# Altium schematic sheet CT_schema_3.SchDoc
size 461 x 327 mm
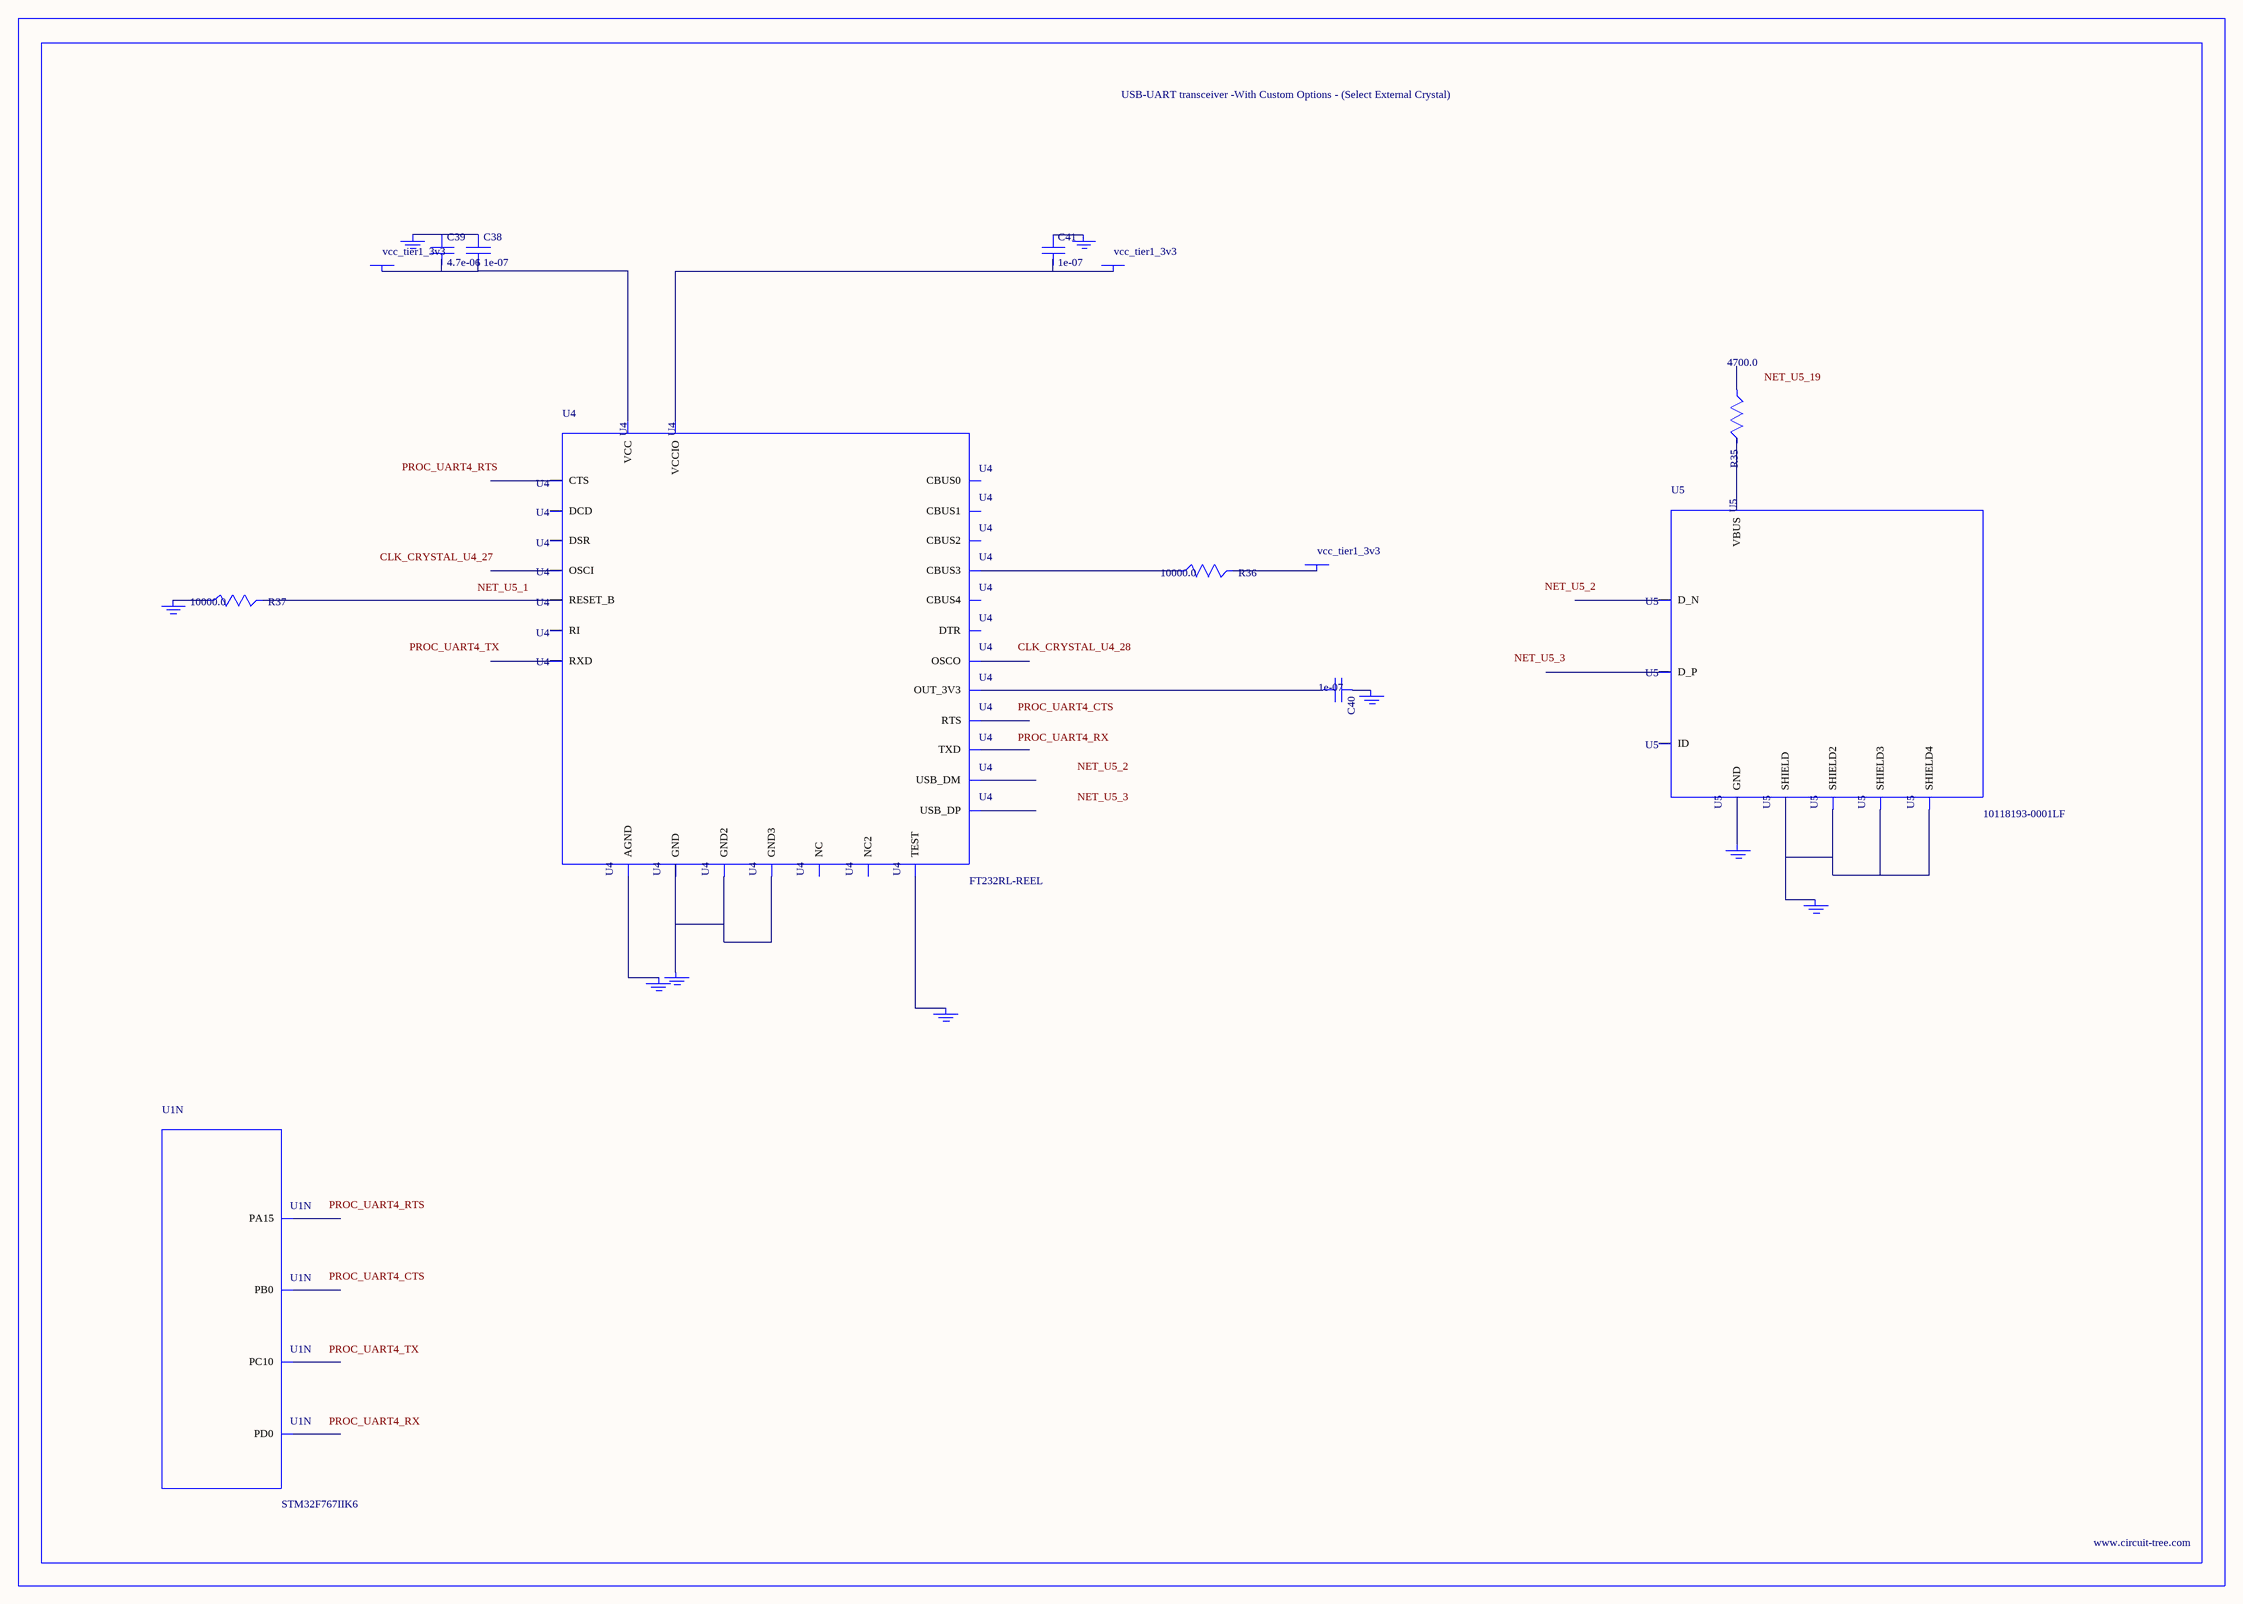
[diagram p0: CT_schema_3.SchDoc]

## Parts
BORDER2  (no value)
C38  1e-07  [C0402]
C39  4.7e-06  [C0805]
C40  1e-07  [C0402]
C41  1e-07  [C0402]
GND_INSTANCE_2_0  (no value)
GND_INSTANCE_2_1  (no value)
GND_INSTANCE_2_2  (no value)
GND_INSTANCE_2_3  (no value)
GND_INSTANCE_2_4  (no value)
GND_INSTANCE_2_5  (no value)
GND_INSTANCE_2_6  (no value)
GND_INSTANCE_2_7  (no value)
GND_INSTANCE_2_8  (no value)
POWER_INSTANCE_2_0  vcc_tier1_3v3
POWER_INSTANCE_2_1  vcc_tier1_3v3
POWER_INSTANCE_2_2  vcc_tier1_3v3
R35  4700.0  [R0603]
R36  10000.0  [R0603]
R37  10000.0  [R0603]
U1  STM32F767IIK6  [UFBGA176_25]  (part N of 17)
U4  FT232RL-REEL  [SSOP-28]
U5  10118193-0001LF  [FCI_10118193-0001LF]

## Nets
NetC38_1: C38.1 C39.1 GND_INSTANCE_2_3.0(GND)
NetC38_2: C38.2 C39.2 POWER_INSTANCE_2_2.0(PWR) U4.20(VCC)
NetC40_1: C40.1 GND_INSTANCE_2_1.0(GND)
NetC40_2: C40.2 U4.17(OUT_3V3)
NetC41_1: C41.1 GND_INSTANCE_2_0.0(GND)
NetC41_2: C41.2 POWER_INSTANCE_2_0.0(PWR) U4.4(VCCIO)
NetGND_INSTANCE_2_2_0: GND_INSTANCE_2_2.0(GND) R37.1
NetGND_INSTANCE_2_4_0: GND_INSTANCE_2_4.0(GND) U4.25(AGND)
NetGND_INSTANCE_2_5_0: GND_INSTANCE_2_5.0(GND) U4.26(TEST)
NetGND_INSTANCE_2_6_0: GND_INSTANCE_2_6.0(GND) U4.7(GND) U4.18(GND2) U4.21(GND3)
NetGND_INSTANCE_2_7_0: GND_INSTANCE_2_7.0(GND) U5.6(SHIELD) U5.7(SHIELD2) U5.8(SHIELD3) U5.9(SHIELD4)
NetGND_INSTANCE_2_8_0: GND_INSTANCE_2_8.0(GND) U5.5(GND)
NetPOWER_INSTANCE_2_1_0: POWER_INSTANCE_2_1.0(PWR) R36.2
NetR35_2: R35.2 U5.1(VBUS)
NetR36_1: R36.1 U4.14(CBUS3)
NetR37_2: R37.2 U4.19(RESET_B)

Not connected (* = marked no-connect by the designer): R35 1; U1 A13(PA15) B12(PD0) B14(PC10) R5(PB0); U4 1(TXD) 2(DTR) 3(RTS) 5(RXD) 6(RI) 8(NC) 9(DSR) 10(DCD) 11(CTS) 12(CBUS4) 13(CBUS2) 15(USB_DP) 16(USB_DM) 22(CBUS1) 23(CBUS0) 24(NC2) 27(OSCI) 28(OSCO); U5 2(D_N) 3(D_P) 4(ID)

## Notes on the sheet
- Labels drawn without touching a wire or pin: CLK_CRYSTAL_U4_27, CLK_CRYSTAL_U4_28, NET_U5_1, NET_U5_2, NET_U5_3, NET_U5_19, PROC_UART4_CTS, PROC_UART4_RTS, PROC_UART4_RX, PROC_UART4_TX

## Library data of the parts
BORDER2 = BORDER_PAGE2
C38 C40 C41 = C0402C104K3RACTU
C39 = C0805C475K4RACTU
GND_INSTANCE_2_0-GND_INSTANCE_2_8 = GND
POWER_INSTANCE_2_0-POWER_INSTANCE_2_2 = PWR
R35 = RC0603JR-074K7L
R36 R37 = RC0603JR-0710KL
